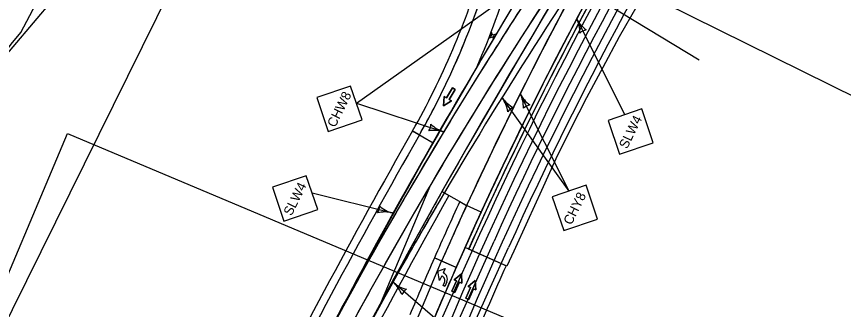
# Model space of a CAD drawing. Extents: x 14104283 to 14120882, y 8635219 to 8671666.
# Drawn here: x 14118626 to 14119252, y 8668473 to 8668695 of the extents above; entities that cross this region are included whole.
import ezdxf

# ---------------------------------------------------------------- set-up
doc = ezdxf.new("R2010")
doc.units = 0
for name, color, linetype in [('Cell', 7, 'Continuous'), ('dsnNonPlotable', 7, 'Continuous'), ('dsnPaintExistingEdgeLineLeftYellow', 7, 'Continuous'), ('dsnPaintExistingLaneLineWhite', 7, 'Continuous'), ('dsnPaintPlaceBrokenLineWhite', 7, 'Continuous'), ('dsnPaintPlaceChannelizingLaneWhite', 7, 'Continuous'), ('dsnPaintPlaceChannelizingLaneYellow', 7, 'Continuous'), ('dsnPaintPlaceEdgeLineLeftYellow', 7, 'Continuous'), ('dsnPaintPlaceEdgeLineRightWhite', 7, 'Continuous'), ('dsnPaintPlaceLaneLineWhite', 7, 'Continuous'), ('dsnPaintRemoveDoubleCenterLineYellow', 7, 'Continuous'), ('dsnPaintRemoveEdgeLineWhite', 7, 'Continuous'), ('dsnShadingPaved', 7, 'Continuous'), ('dsnStdLabel', 7, 'Continuous'), ('dsnStgShadingPrevPav', 7, 'Continuous'), ('dsnTapePlaceChannelizingLaneWhite', 7, 'Continuous'), ('dsnTapePlaceChannelizingLaneYellow', 7, 'Continuous'), ('dsnTapePlaceEdgeLineLeftYellow', 7, 'Continuous'), ('dsnTapeRemoveChannelizingWhite', 7, 'Continuous'), ('dsnTapeRemoveDoubleCenterLineYellow', 7, 'Continuous'), ('dsnTextFinalPlan', 7, 'Continuous'), ('Level 2', 7, 'Continuous'), ('Level 5', 7, 'Continuous'), ('Terrain', 7, 'Continuous')]:
    doc.layers.add(name, color=color, linetype=linetype)

msp = doc.modelspace()

# ---------------------------------------------------------------- linework, layer by layer
at = {"layer": 'Cell'}
for p, q in [((14118984.85, 8668680.15), (14118984.36, 8668678.87)), ((14118984.36, 8668678.87), (14118986.54, 8668679.84)), ((14118986.22, 8668680.56), (14118984.85, 8668680.15)), ((14118985.98, 8668683.07), (14118985.49, 8668681.79)), ((14118985.49, 8668681.79), (14118986.22, 8668680.56)), ((14118986.95, 8668680.89), (14118985.98, 8668683.07)), ((14118986.54, 8668679.84), (14118987.51, 8668677.65)), ((14118989.13, 8668681.85), (14118986.95, 8668680.89)), ((14118987.27, 8668680.16), (14118988.63, 8668680.57)), ((14118988, 8668678.94), (14118987.27, 8668680.16)), ((14118988.63, 8668680.57), (14118989.13, 8668681.85)), ((14118987.51, 8668677.65), (14118988, 8668678.94)), ((14118948.51, 8668498.6), (14118948.22, 8668498.72)), ((14118949.36, 8668501.09), (14118949.53, 8668501.02))]:
    msp.add_line(p, q, dxfattribs=at)
for points in [[(14118945.2, 8668502.27), (14118950.96, 8668504.41), (14118949.36, 8668501.09)], [(14118945.2, 8668502.27), (14118950.96, 8668504.41), (14118949.36, 8668501.09)], [(14118948.22, 8668498.72), (14118946.62, 8668495.4), (14118945.2, 8668502.27)], [(14118948.22, 8668498.72), (14118946.62, 8668495.4), (14118945.2, 8668502.27)], [(14118948.51, 8668498.6), (14118948.22, 8668498.72)], [(14118949.36, 8668501.09), (14118949.53, 8668501.02)], [(14118952.08, 8668494.24), (14118950.65, 8668490.85), (14118949.27, 8668491.43), (14118950.29, 8668493.85)], [(14118952.08, 8668494.24), (14118950.65, 8668490.85), (14118949.27, 8668491.43), (14118950.29, 8668493.85)]]:
    msp.add_lwpolyline(points, dxfattribs=at)
for centre, major_axis in [((14118947.08, 8668495.21), (-1.43, -3.39)), ((14118947.08, 8668495.21), (-1.43, -3.39)), ((14118947.49, 8668496.17), (-2.04, -4.84)), ((14118947.49, 8668496.17), (-2.04, -4.84))]:
    msp.add_ellipse(centre, major_axis=major_axis, ratio=0.9474, start_param=1.570796, end_param=3.141593, dxfattribs=at)
at = {"layer": 'dsnNonPlotable'}
for points in [[(14118631.64, 8668945.1), (14119326.37, 8670350.23), (14120231.75, 8669902.59), (14119537.02, 8668497.46)], [(14118056.48, 8667161.91), (14118665.06, 8668606.45), (14119130.44, 8668410.38), (14118521.87, 8666965.84)]]:
    msp.add_lwpolyline(points, close=True, dxfattribs=at)
at = {"layer": 'dsnPaintExistingEdgeLineLeftYellow'}
msp.add_line((14118852.57, 8668283.93), (14118948.15, 8668509.94), dxfattribs=at)
at = {"layer": 'dsnPaintExistingLaneLineWhite'}
msp.add_arc((14121592.11, 8667345.68), 2876.95, 153.70867, 157.1633, dxfattribs=at)
at = {"layer": 'dsnPaintPlaceBrokenLineWhite'}
for centre, radius, start, end in [((14121592.11, 8667345.68), 2864.95, 147.15737, 157.1633), ((14121955.85, 8666791.92), 3500, 144.95493, 149.50762), ((14121955.85, 8666791.92), 3500, 149.50762, 152.69211)]:
    msp.add_arc(centre, radius, start, end, dxfattribs=at)
at = {"layer": 'dsnPaintPlaceChannelizingLaneWhite'}
msp.add_arc((14118409.81, 8668902.17), 616, 336.56541, 343.63038, dxfattribs=at)
at = {"layer": 'dsnPaintPlaceChannelizingLaneYellow'}
msp.add_arc((14121592.11, 8667345.68), 2888.95, 151.25989, 155.3184, dxfattribs=at)
at = {"layer": 'dsnPaintPlaceEdgeLineLeftYellow'}
msp.add_arc((14121592.11, 8667345.68), 2888.95, 155.3184, 156.23389, dxfattribs=at)
at = {"layer": 'dsnPaintPlaceEdgeLineRightWhite'}
for centre, radius, start, end in [((14121592.11, 8667345.68), 2852.95, 147.15737, 157.1633), ((14118409.81, 8668902.17), 600, 334.79009, 343.63038), ((14118421.29, 8668896.21), 587.08, 330.32024, 334.83876), ((14123732.96, 8665874.38), 5524, 150.3689, 156.09858)]:
    msp.add_arc(centre, radius, start, end, dxfattribs=at)
at = {"layer": 'dsnPaintPlaceLaneLineWhite'}
for centre, radius, start, end in [((14121592.11, 8667345.68), 2876.95, 151.25989, 153.70867), ((14122745.39, 8666422.79), 4382.73, 149.34837, 152.56312)]:
    msp.add_arc(centre, radius, start, end, dxfattribs=at)
at = {"layer": 'dsnPaintRemoveDoubleCenterLineYellow'}
msp.add_arc((14121592.11, 8667345.68), 2858.95, 147.15737, 155.63386, dxfattribs=at)
at = {"layer": 'dsnPaintRemoveEdgeLineWhite'}
for p, q in [((14118976.89, 8668530.13), (14118962.39, 8668498.19)), ((14118983.89, 8668487.5), (14118998.75, 8668520.22))]:
    msp.add_line(p, q, dxfattribs=at)
for centre, radius, start, end in [((14121639.53, 8667321.97), 2923.92, 146.37023, 155.59399), ((14121592.11, 8667345.68), 2846.95, 147.15737, 155.63407)]:
    msp.add_arc(centre, radius, start, end, dxfattribs=at)
at = {"layer": 'dsnShadingPaved'}
for p, q in [((14118900.6, 8668474.65), (14118939.91, 8668567.91)), ((14118900.6, 8668474.65), (14118939.91, 8668567.91)), ((14118852.57, 8668283.93), (14118948.15, 8668509.94))]:
    msp.add_line(p, q, dxfattribs=at)
for centre, radius, start, end in [((14121592.11, 8667345.68), 2876.95, 147.15737, 157.1633), ((14121592.11, 8667345.68), 2852.95, 147.15737, 157.1633), ((14121955.85, 8666791.92), 3512, 144.95493, 152.69211), ((14121955.85, 8666791.92), 3500, 144.95493, 152.69211), ((14121955.85, 8666791.92), 3500, 144.95493, 149.50762), ((14121955.85, 8666791.92), 3488, 144.95493, 149.50762), ((14118409.81, 8668902.17), 600, 330.3689, 343.63038), ((14121592.11, 8667345.68), 2888.95, 151.25989, 155.3184), ((14121592.11, 8667345.68), 2876.95, 151.25989, 157.1633), ((14118409.81, 8668902.17), 616, 336.56541, 343.63038), ((14123732.96, 8665874.38), 5512, 149.67774, 156.09858), ((14123732.96, 8665874.38), 5524, 150.3689, 153.23374), ((14121955.85, 8666791.92), 3500, 149.50762, 152.69211), ((14121955.85, 8666791.92), 3488, 149.50762, 151.15555), ((14121592.11, 8667345.68), 2888.95, 155.3184, 156.23389), ((14121955.85, 8666791.92), 3488, 151.15555, 152.69211)]:
    msp.add_arc(centre, radius, start, end, dxfattribs=at)
at = {"layer": 'dsnStdLabel'}
for p, q in [((14118883.62, 8668629.6), (14118993.74, 8668707.57)), ((14119086.88, 8668620.85), (14119050.38, 8668693.42)), ((14119044.66, 8668563.01), (14119007.64, 8668636.6)), ((14118883.62, 8668629.6), (14118949.55, 8668607.87)), ((14119044.66, 8668563.01), (14118994.11, 8668633.41)), ((14118850.06, 8668561.72), (14118910.88, 8668546.47)), ((14118981.16, 8668434.03), (14118911.62, 8668493.66))]:
    msp.add_line(p, q, dxfattribs=at)
for points in [[(14118862.37, 8668608.16), (14118887.94, 8668616.82), (14118879.29, 8668642.39), (14118853.71, 8668633.74)], [(14119082.74, 8668590.95), (14119108.32, 8668599.6), (14119099.67, 8668625.18), (14119074.09, 8668616.53)], [(14118828.81, 8668540.28), (14118854.38, 8668548.94), (14118845.73, 8668574.51), (14118820.15, 8668565.86)], [(14119040.52, 8668533.11), (14119066.1, 8668541.76), (14119057.45, 8668567.34), (14119031.87, 8668558.68)]]:
    msp.add_lwpolyline(points, close=True, dxfattribs=at)
for centre, radius, start, end in [((14119029.87, 8668683.1), 22.95, 358.63396, 26.70527), ((14119070.88, 8668703.73), 22.95, 206.70512, 234.77638), ((14119059.02, 8668676.23), 8.86, 98.97095, 134.4394), ((14118987.13, 8668626.29), 22.95, 358.63396, 26.70527), ((14119028.14, 8668646.92), 22.95, 206.70512, 234.77638), ((14118975.47, 8668620.03), 22.95, 7.60675, 35.67806), ((14119012.75, 8668646.8), 22.95, 215.6779, 243.74917), ((14119005.33, 8668617.78), 8.86, 107.94373, 143.41218), ((14119016.28, 8668619.41), 8.86, 98.97095, 134.4394), ((14118931.23, 8668613.71), 8.86, 324.4828, 359.95125), ((14118956.56, 8668629.69), 22.95, 224.14582, 252.21712), ((14118942.54, 8668585.98), 22.95, 72.21697, 100.28824), ((14118892.22, 8668551.15), 8.86, 328.18608, 3.65453), ((14118916.47, 8668568.73), 22.95, 227.84909, 255.9204), ((14118905.3, 8668524.21), 22.95, 75.92025, 103.99151), ((14118896.68, 8668476.23), 22.95, 21.31899, 49.3903), ((14118926.56, 8668511.08), 22.95, 229.39015, 257.46141), ((14118926.22, 8668481.13), 8.86, 121.65598, 157.12443)]:
    msp.add_arc(centre, radius, start, end, dxfattribs=at)
at = {"layer": 'dsnStgShadingPrevPav'}
for p, q in [((14118926.13, 8668608.49), (14118941.74, 8668599.61)), ((14118931.35, 8668605.52), (14118926.13, 8668608.49)), ((14118926.13, 8668608.49), (14118941.74, 8668599.61)), ((14118967.09, 8668552.03), (14118948.39, 8668562.54)), ((14118948.4, 8668562.54), (14118953.63, 8668559.6)), ((14118961.85, 8668554.98), (14118967.09, 8668552.03)), ((14118978, 8668547.02), (14118967.09, 8668552.03)), ((14118996.9, 8668506.38), (14118965.9, 8668520.25)), ((14118968.62, 8668519.03), (14118965.92, 8668520.24)), ((14118997.49, 8668506.12), (14118968.61, 8668519.04)), ((14118948.15, 8668509.93), (14118942.66, 8668512.35)), ((14118959.14, 8668505.1), (14118948.15, 8668509.93))]:
    msp.add_line(p, q, dxfattribs=at)
for points in [[(14119103.24, 8668715.93), (14119095.89, 8668702.99), (14119082.56, 8668679.77), (14119070.05, 8668656.56), (14119057.76, 8668633.47), (14119046.28, 8668610.93), (14119034.69, 8668587.34), (14119023.78, 8668563.4), (14119013.09, 8668540.14), (14119002.78, 8668517.49), (14118997.49, 8668506.12)], [(14118965.9, 8668520.25), (14118959.14, 8668505.1), (14118942.66, 8668512.35)]]:
    msp.add_lwpolyline(points, dxfattribs=at)
for centre, radius, start, end in [((14123732.96, 8665874.38), 5512, 146.42562, 157.1633), ((14123732.59, 8665873.82), 5512, 146.50213, 150.36196), ((14123732.96, 8665874.38), 5488, 146.42119, 157.1633), ((14121592.11, 8667345.68), 2888.95, 147.23666, 156.23389), ((14123732.85, 8665874.2), 5488.01, 146.41277, 150.66874), ((14121592.13, 8667345.67), 2876.95, 147.18034, 155.90343), ((14121592.11, 8667345.68), 2888.95, 147.23666, 155.3184), ((14121592.11, 8667345.68), 2876.95, 147.24009, 156.23389), ((14121592.13, 8667345.67), 2873.95, 147.18114, 155.90343), ((14118409.81, 8668902.17), 594, 330.3689, 343.63038), ((14121592.11, 8667345.68), 2873.95, 151.16499, 155.90343), ((14123732.96, 8665874.38), 5530, 150.3689, 156.09911), ((14123732.96, 8665874.38), 5524, 150.3689, 156.09858), ((14123732.96, 8665874.38), 5524, 150.3689, 156.09858), ((14123732.59, 8665873.82), 5512, 150.36196, 157.1633), ((14123732.96, 8665874.38), 5488, 150.67095, 151.14296), ((14123732.96, 8665874.38), 5482, 150.67101, 157.1633), ((14121592.11, 8667345.68), 2894.95, 155.30872, 156.23384), ((14121592.11, 8667345.68), 2888.95, 155.3184, 156.23389), ((14123732.96, 8665874.38), 5488, 151.14296, 157.1633), ((14121592.11, 8667345.68), 2894.95, 156.23384, 157.1633), ((14121592.11, 8667345.68), 2842.95, 155.90343, 157.1633)]:
    msp.add_arc(centre, radius, start, end, dxfattribs=at)
at = {"layer": 'dsnTapePlaceChannelizingLaneWhite'}
for start, end in [(145.38458, 147.96378), (147.96378, 151.97273)]:
    msp.add_arc((14121955.85, 8666791.92), 3512, start, end, dxfattribs=at)
at = {"layer": 'dsnTapePlaceChannelizingLaneYellow'}
msp.add_arc((14121955.85, 8666791.92), 3488, 144.95493, 149.50762, dxfattribs=at)
at = {"layer": 'dsnTapePlaceEdgeLineLeftYellow'}
msp.add_arc((14121955.85, 8666791.92), 3488, 149.50762, 152.69211, dxfattribs=at)
at = {"layer": 'dsnTapeRemoveChannelizingWhite'}
for p, q in [((14118962.39, 8668498.19), (14118840.41, 8668224.15)), ((14118862.53, 8668214.84), (14118984.08, 8668487.9))]:
    msp.add_line(p, q, dxfattribs=at)
at = {"layer": 'dsnTapeRemoveDoubleCenterLineYellow'}
msp.add_line((14118851.47, 8668219.49), (14118987.82, 8668525.18), dxfattribs=at)
at = {"layer": 'dsnTextFinalPlan'}
msp.add_line((14118914.55, 8668801.16), (14119143.05, 8668662.37), dxfattribs=at)
msp.add_lwpolyline([(14118092.03, 8667853.71), (14118606.59, 8668894.44), (14118787.23, 8668805.14), (14118272.66, 8667764.4)], close=True, dxfattribs=at)
at = {"layer": 'Level 2'}
for points in [[(14118958.44, 8668639.87), (14118956.29, 8668641.15), (14118951.81, 8668633.63), (14118950.2, 8668634.6), (14118949.68, 8668627.63), (14118955.57, 8668631.39), (14118953.96, 8668632.35)], [(14118955.91, 8668487.14), (14118958.2, 8668486.13), (14118961.73, 8668494.13), (14118963.45, 8668493.38), (14118963.11, 8668500.36), (14118957.73, 8668495.9), (14118959.45, 8668495.15)], [(14118966.4, 8668481.95), (14118968.69, 8668480.94), (14118972.22, 8668488.95), (14118973.94, 8668488.19), (14118973.61, 8668495.17), (14118968.22, 8668490.71), (14118969.94, 8668489.96)]]:
    msp.add_lwpolyline(points, close=True, dxfattribs=at)
at = {"layer": 'Level 5'}
for points in [[(14118953.96, 8668632.35), (14118955.57, 8668631.39), (14118949.68, 8668627.63), (14118950.2, 8668634.6), (14118951.81, 8668633.63), (14118956.29, 8668641.15), (14118958.44, 8668639.87), (14118953.96, 8668632.35)], [(14118959.45, 8668495.15), (14118957.73, 8668495.9), (14118963.11, 8668500.36), (14118963.45, 8668493.38), (14118961.73, 8668494.13), (14118958.2, 8668486.13), (14118955.91, 8668487.14), (14118959.45, 8668495.15)], [(14118969.94, 8668489.96), (14118968.22, 8668490.71), (14118973.61, 8668495.17), (14118973.94, 8668488.19), (14118972.22, 8668488.95), (14118968.69, 8668480.94), (14118966.4, 8668481.95), (14118969.94, 8668489.96)]]:
    msp.add_lwpolyline(points, dxfattribs=at)
at = {"layer": 'Terrain'}
for points in [[(14118599.79, 8668640.48), (14118608.32, 8668654.13), (14118654.78, 8668708.88), (14118678.97, 8668737.39), (14118696.75, 8668773.34), (14118700.24, 8668798.42), (14118703.85, 8668824.42)], [(14118533.97, 8668521.11), (14118537.05, 8668526.7), (14118540.07, 8668533.13), (14118557.76, 8668570.81), (14118572.99, 8668598.24), (14118580.77, 8668612.66), (14118593.46, 8668634.1), (14118601.01, 8668645.72), (14118622.27, 8668674.24), (14118629.71, 8668683.08), (14118678.25, 8668774.93)]]:
    msp.add_lwpolyline(points, dxfattribs=at)

# ---------------------------------------------------------------- texts
at = {"layer": 'dsnStdLabel'}
for s, p in [('CHW8', (14118867.59, 8668610.61)), ('SLW4', (14119088.47, 8668594.41)), ('SLW4', (14118834.53, 8668543.75)), ('CHY8', (14119046.36, 8668536.8))]:
    msp.add_text(s, height=7.2, rotation=63.69117, dxfattribs=at).set_placement(p)

doc.saveas('drawing.dxf')
